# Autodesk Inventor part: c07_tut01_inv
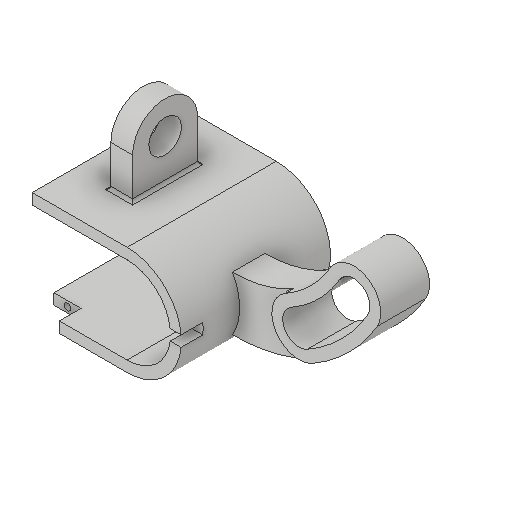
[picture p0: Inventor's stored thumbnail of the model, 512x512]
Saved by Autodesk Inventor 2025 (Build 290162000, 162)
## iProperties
Created: 2017-04
Part Number: c07_tut01_inv
Material: Generic
Document SubType Name: Modeling
Designer: CADCIM 00
Density: 1 g/cm^3
Appearance: Default
Author: CADCIM 00
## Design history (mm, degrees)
sketch "Sketch1"
  geometry: L1 (0, 16)-(35, 16); L2 (35, 16)-(35, 20); L3 (35, 20)-(0, 20); L4 (0, -20)-(35, -20); L5 (35, -20)-(35, -16); L6 (35, -16)-(0, -16); A1 r 16 centre (0, 0) between (0, 16) and (0, -16); A2 r 20 centre (0, 0) between (0, 20) and (0, -20); 1 further point
  constraints: 12 end point, 4 point on circle, 4 tangent, 3 perpendicular, 2 centre point, 2 point on line, 1 coincident, 1 concentric, 1 horizontal, 1 parallel
  dimensions: "d1" = 20 radius of A2; "d3" = 35 distance from line of point (0, 0) L5; "d37" = 16 radius of A1
extrude "Extrusion1" new body sketch "Sketch1" stored distance "d4" = 55; taper "d5" = 0 deg
sketch "Sketch2"
  geometry: A1 r 45 centre (-17.5, 55) between (-56.409, 32.393) and (-17.32, 10); A2 r 65 centre (-17.5, 55) between (-73.702, 22.345) and (-17.321, -10); A3 r 10 centre (-65.055, 27.369) between (-56.409, 32.393) and (-73.702, 22.345); A4 r 20 centre (0, 0) between (0, 20) and (0, -20) reference; A5 r 20 centre (0, 0) between (-17.32, 10) and (-17.321, -10); 1 further point
  constraints: 10 point on circle, 4 centre point, 2 tangent, 1 coincident
  dimensions: "d6" = 45 radius of A1; "d7" = 65 radius of A2; "d8" = 17.5 horizontal distance of point (0, 0) A1.centre; "d9" = 55 vertical distance of point (0, 0) A1.centre; "d10" = 60 deg dimension on A1.centre A3.centre A2.end
extrude "Extrusion2" join sketch "Sketch2" stored distance "d11" = 12; taper "d12" = 0 deg
sketch "Sketch3"
  geometry: A1 r 55 centre (-17.5, 55) between (-65.055, 27.369) and (-44.868, 7.293); A2 r 65 centre (-17.5, 55) between (-73.702, 22.345) and (-49.845, -1.381); A3 r 45 centre (-17.5, 55) between (-56.409, 32.393) and (-39.892, 15.967); A4 r 10 centre (-65.055, 27.369) between (-56.409, 32.393) and (-73.702, 22.345); A5 r 10 centre (-44.868, 7.293) between (-49.845, -1.381) and (-39.892, 15.967); A6 r 45 centre (-17.5, 55) between (-56.409, 32.393) and (-17.32, 10) reference; A7 r 65 centre (-17.5, 55) between (-73.702, 22.345) and (-17.321, -10) reference; A8 r 10 centre (-65.055, 27.369) between (-56.409, 32.393) and (-73.702, 22.345) reference; 1 further point
  constraints: 10 point on circle, 7 tangent, 5 centre point, 1 concentric
  dimensions: "d13" = 30 deg dimension on A1.centre A1.end A1.start
extrude "Extrusion3" join sketch "Sketch3" stored distance "d14" = 18; taper "d15" = 0 deg
sketch "Sketch4"
  geometry: A1 r 55 centre (17.5, 55) between (44.868, 7.293) and (65.055, 27.369); A2 r 61 centre (17.5, 55) between (47.854, 2.088) and (70.243, 24.354); A3 r 49 centre (17.5, 55) between (41.883, 12.497) and (59.867, 30.383); A4 r 6 centre (44.868, 7.293) between (41.883, 12.497) and (47.854, 2.088); A5 r 6 centre (65.055, 27.369) between (70.243, 24.354) and (59.867, 30.383); A6 r 45 centre (17.5, 55) between (39.892, 15.967) and (56.409, 32.393) reference; A7 r 10 centre (65.055, 27.369) between (73.702, 22.345) and (56.409, 32.393) reference; A8 r 10 centre (44.868, 7.293) between (39.892, 15.967) and (49.845, -1.381) reference; 1 further point
  constraints: 10 point on circle, 5 centre point, 4 tangent, 3 concentric
  dimensions: "d16" = 6 radius of A5
extrude "Extrusion4" cut sketch "Sketch4" extent not by distance; stored distance "d17" = 18; taper "d18" = 0 deg
workplane "Work Plane1"
sketch "Sketch5"
  geometry: L1 (0, 39.5)-(15, 39.5); L2 (15, 15.5)-(0, 15.5); L3 (0, 55)-(0, 0) reference; L4 (0, 39.5)-(0, 15.5); L5 (-40, 0)-(0, 0) reference; C1 r 6 at (15, 27.5); A1 r 12 centre (15, 27.5) between (15, 15.5) and (15, 39.5); 1 further point
  constraints: 6 end point, 2 centre point, 2 point on circle, 2 point on line, 2 tangent, 1 coincident, 1 collinear, 1 horizontal, 1 parallel
  dimensions: "d20" = 12 radius of A1; "d21" = 12 diameter of C1; "d22" = 15 distance from line of L3 A1.centre; "d23" = 27.5 distance from line of L5 A1.centre
extrude "Extrusion5" join sketch "Sketch5" distance "d24" = 8; taper "d25" = 0 deg
fillet "Fillet1" dims "d26" = 1
sketch "Sketch6"
  geometry: L1 (-35, -16)-(-35, -20) reference; L2 (-35, -20)-(0, -20) reference; L3 (-35, -16)-(-25, -16); L4 (-25, -16)-(-25, -20); L5 (-25, -20)-(-35, -20); L6 (-35, -20)-(-35, -16); L7 (15.631, 2)-(21.208, 2); L8 (21.208, 2)-(21.208, -2); L9 (21.208, -2)-(15.631, -2); L10 (15.631, -2)-(15.631, 2); A1 r 20 centre (0, 0) between (0, -20) and (0, 20) reference; 1 further point
  constraints: 16 end point, 4 parallel, 2 horizontal, 1 perpendicular, 1 point on line
  dimensions: "d27" = 10 distance of L1.start L3.end; "d28" = 4 distance of L9.end L7.start; "d29" = 2 distance from line of L7 point (0, 0)
extrude "Extrusion6" cut sketch "Sketch6" distance "d30" = 8; taper "d31" = 0 deg
sketch "Sketch7"
  geometry: L1 (-35, -20)-(-35, -16) reference; L2 (-25, -20)-(-35, -20) reference; C1 r 1.25 at (-30, -18); 1 further point
  constraints: 1 centre point
  dimensions: "d32" = 5 distance from line of L1 C1.centre; "d33" = 2 distance from line of L2 C1.centre; "d34" = 2.5 diameter of C1
extrude "Extrusion7" cut sketch "Sketch7" distance "d35" = 4; taper "d36" = 0 deg
body "Solid1"
other parameters: "d19" = -13.5
